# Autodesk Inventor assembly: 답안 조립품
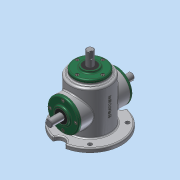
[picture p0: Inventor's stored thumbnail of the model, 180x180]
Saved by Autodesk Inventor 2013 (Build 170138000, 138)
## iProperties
Created: 2018-04
Part Number: 답안 조립품
Document SubType Name: Assembly
Designer: dgall
Author: dgall
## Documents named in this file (16)
- C:\Users\dgall\Desktop\480407V1021\답안 조립품.iam
- C:\Users\dgall\Desktop\480407V1021\본체.ipt
- C:\Users\dgall\Desktop\480407V1021\메인 축.ipt
- 메인 축.ipt
- C:\Users\dgall\Desktop\480407V1021\키 5x5.ipt
- C:\Users\dgall\Desktop\480407V1021\커버.ipt
- C:\Users\dgall\Desktop\480407V1021\베어링 6203.ipt
- C:\Users\dgall\Desktop\480407V1021\오일 실.ipt
- 오일 실.ipt
- C:\Users\dgall\Desktop\480407V1021\메인 베벨기어.ipt
- C:\Users\dgall\Desktop\480407V1021\서브 베벨기어.ipt
- C:\Users\dgall\Desktop\480407V1021\서브 축.ipt
- 서브 축.ipt
- C:\Users\dgall\Desktop\480407V1021\키 4x4.ipt
- C:\Users\dgall\Desktop\480407V1021\볼트 M4.ipt
- 볼트 M4.ipt
